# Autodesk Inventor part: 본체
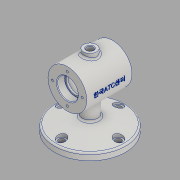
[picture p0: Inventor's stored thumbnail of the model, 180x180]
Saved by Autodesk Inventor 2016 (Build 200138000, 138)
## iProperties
Created: 2018-12
Part Number: 본체
Material: 알루미늄 6061
Document SubType Name: Modeling
Designer: 605-08
Density: 2.7 g/cm^3
Appearance: 알루미늄 - 평지
Author: 605-08
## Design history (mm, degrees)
sketch "스케치1"
  geometry: L1 (-35, 30)-(35, 30); L2 (35, 30)-(35, 0); L3 (35, 0)-(-35, 0); L4 (-35, 0)-(-35, 30); L5 (-35, 16)-(-23, 16); L6 (-23, 16)-(-23, 14); L7 (-23, 14)-(-20, 14); L8 (-20, 14)-(-20, 25); L9 (-20, 25)-(20, 25); L10 (20, 25)-(20, 14); L11 (20, 14)-(23, 14); L12 (23, 14)-(23, 16); L13 (23, 16)-(35, 16); 2 further points
  constraints: 26 end point, 10 perpendicular, 2 collinear, 2 parallel, 2 point on line, 1 coincident, 1 horizontal, 1 midpoint
  dimensions: "d0" = 70 distance between parallel lines of L2 L4; "d1" = 12 distance between parallel lines of L6 L4; "d2" = 12 distance between parallel lines of L2 L12; "d3" = 32 diameter of L5 L3; "d4" = 28 diameter of L7 L3; "d5" = 50 diameter of L9 L3; "d6" = 40 distance between parallel lines of L10 L8; "d7" = 60 diameter of L1 L3; "d8" = 3 distance between parallel lines of L12 L10
revolve "회전1" sketch "스케치1" stored, may be unused: angle "d9" = 90 deg
fillet "모깎기1" dims "d10" = 3, "d11" = 0.3
chamfer "모따기1" distance "d12" = 1; stored, may be unused: second distance "d13" = 2, angle "d14" = 45 deg
node "작업 평면1"
sketch "스케치2"
  geometry: C1 r 55 at (0, 0); 1 further point
  constraints: 1 centre point, 1 coincident
  dimensions: "d16" = 110 diameter of C1
extrude "돌출1" join sketch "스케치2" distance "d17" = 22; taper "d18" = 0 deg
sketch "스케치6" dims "d39" = 88
  geometry: L1 (0, 0)-(0, -44); 2 further points
  constraints: 2 coincident, 2 end point, 1 vertical, 1 vertical alignment, 2 other
hole "구멍2" sketch "스케치6" at (0, -44) diameter "d40" = 9; stored, may be unused: countersink angle "d44" = 90 deg, drill point angle "d46" = 0 deg; dims "d41" = 6, "d42" = 14, "d43" = 12, "d45" = 8
node "작업 평면2"
sketch "스케치4"
  geometry: C1 r 10 at (0, 0); 1 further point
  constraints: 1 centre point, 1 coincident
  dimensions: "d26" = 20 diameter of C1
extrude "돌출3" join sketch "스케치4" stored distance "d27" = 10; taper "d28" = 0 deg
hole "구멍1" diameter "d31" = 10; stored, may be unused: countersink angle "d35" = 90 deg, drill point angle "d37" = 0 deg; dims "d29" = 10, "d30" = 10, "d32" = 6, "d33" = 4, "d34" = 2, "d36" = 8
sketch "스케치7" dims "d50" = 46
  geometry: L1 (0, 0)-(-23, 0); 2 further points
  constraints: 2 coincident, 2 end point, 1 horizontal, 1 horizontal alignment, 2 other
hole "구멍3" sketch "스케치7" at (-23, 0) diameter "d51" = 3.242; stored, may be unused: countersink angle "d55" = 90 deg, drill point angle "d57" = 118 deg; dims "d52" = 8, "d53" = 14, "d54" = 12, "d56" = 10
sketch "스케치10"
  geometry: C1 r 12 at (0, 0); 1 further point
  constraints: 1 centre point, 1 coincident
  dimensions: "d68" = 24 diameter of C1
extrude "돌출6" join sketch "스케치10" stored distance "d69" = 10; taper "d70" = 0 deg
chamfer "모따기3" distance "d71" = 11.52; stored, may be unused: second distance "d72" = 2, angle "d73" = 75 deg
fillet "모깎기2" dims "d74" = 3
fillet "모깎기3" dims "d75" = 3
chamfer "모따기4" distance "d76" = 1; stored, may be unused: second distance "d77" = 2, angle "d78" = 75 deg
node "작업 평면3"
node "작업 평면4"
sketch "스케치12"
  geometry: L1 (-35, -30)-(-35, 30) reference; L2 (-35, 30)-(35, 30) reference; 2 further points
  constraints: 1 other
  dimensions: "d83" = 35 distance from line of L1 point (0, 0); "d84" = 30 distance from line of L2 point (0, 0)
feature "엠보싱2" sketch "스케치12" dims "d0" = 70, "d1" = 12, "d2" = 12, "d3" = 32, "d4" = 28, "d5" = 50, "d6" = 40, "d7" = 60, "d8" = 3, "d85" = 0.5, "d86" = 0
node "솔리드1"
pattern_circular "원형 패턴1" dims angle "d48" = 360 deg
pattern_circular "원형 패턴2" dims angle "d59" = 360 deg
mirror "대칭1"
other parameters: "d15" = -75, "d25" = 37
